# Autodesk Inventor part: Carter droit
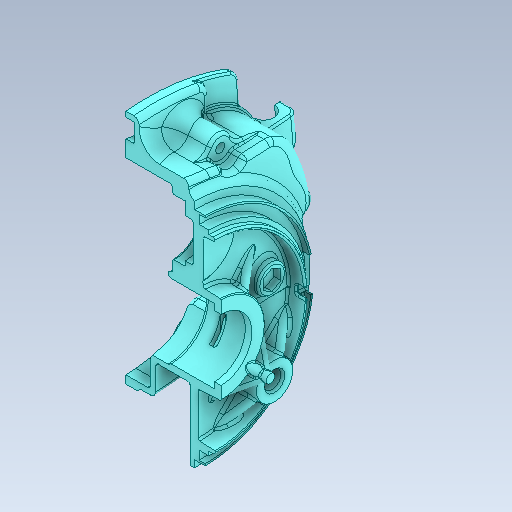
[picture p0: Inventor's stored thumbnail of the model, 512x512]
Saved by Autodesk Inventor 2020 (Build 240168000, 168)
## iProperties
Created: 2003-05
Part Number: Carter droit
Material: Générique
Document SubType Name: Modeling
Designer: Bruno
Density: 1 g/cm^3
Appearance: Par défaut
Author: Bruno
Sending System: SolidWorks 2011
Last Author: Professeur
Last Saved: 2014-11-07
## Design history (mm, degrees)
feature "Enlèv. mat.-Extru.27"
node "Solide1"
